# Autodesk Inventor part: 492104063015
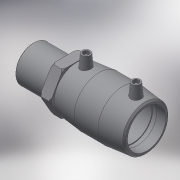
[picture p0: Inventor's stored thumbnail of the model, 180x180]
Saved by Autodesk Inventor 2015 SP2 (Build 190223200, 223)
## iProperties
Created: 2017-06
Part Number: 492104063015
Material: Generic
Description: PLASSON Male Transition Coupler 63 x 1.1/2"
Document SubType Name: Modeling
Designer: KIM
Mass: 337.166 g
Surface Area: 748.954 cm^2
Volume: 337.166 cm^3
Density: 1 g/cm^3
Appearance: Default
Author: KIM
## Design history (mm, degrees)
derived "492104.ipt"
feature "Solid1::492104.ipt"
tag "TaggingFeature1"
body "Solid1"
other parameters: "d0" = 117, "d1" = 63, "d2" = 82, "d3" = 57, "d4" = 39, "d5" = 73.8, "d6" = 59.85, "d7" = 63, "d8" = 168 deg, "d10" = 22.8, "d11" = 7.6, "d29" = 57, "d30" = 14, "d31" = 40.95, "d34" = 5 deg, "d41" = 4, "d42" = 14, "d43" = 0, "d48" = 3, "d49" = 0, "d57" = 48, "d58" = 47.803, "d59" = 38.2424, "d60" = 32.4, "d61" = 82, "d62" = 0.95606, "d65" = 2.46, "d70" = 0.1, "d71" = 36, "d72" = 9, "d73" = 22.8, "d75" = 0, "d_" = 63, "L_" = 153, "L_1" = 57, "D_1" = 82, "A_" = 57, "d_2" = 12, "L_2" = 36, "D_" = 48, "R_" = 47.803
